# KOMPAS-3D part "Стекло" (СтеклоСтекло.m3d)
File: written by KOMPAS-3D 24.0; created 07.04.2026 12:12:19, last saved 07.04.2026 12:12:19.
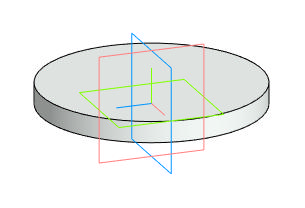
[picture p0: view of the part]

Document properties: Автор: Main; Полное имя файла: D:\DN.ru Аутсерс\Стекло смотровое DN.ru\Исходники\Стекло смотровое DN.ru SG2-34G-F тип В ГОСТ 21836-2021 Ду80 Ру16, углеродистая сталь, фланцевое\СтеклоСтекло.m3d

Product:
- Body: Твердое тело1  | qty 1
- Part/product: Стекло

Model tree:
1. Твердое тело1  (labels: Твердое тело1)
